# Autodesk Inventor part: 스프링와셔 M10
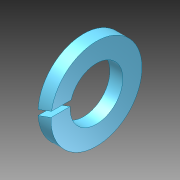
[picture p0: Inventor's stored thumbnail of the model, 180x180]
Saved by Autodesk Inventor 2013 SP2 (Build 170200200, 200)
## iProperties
Created: 2025-04
Part Number: 스프링와셔 M10
Material: Generic
Document SubType Name: Modeling
Designer: 601
Density: 1 g/cm^3
Author: 601
변환 표준: STEP AP214IS
전처리기: Build: 200, Release: 2013 SP2 Update 6 - Date: Thu 07/17/2014
전송 단위: 밀리미터
불확실성: 0.01
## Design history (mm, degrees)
node "스프링와셔 M101"
body "Solid1"
node "기준1"
